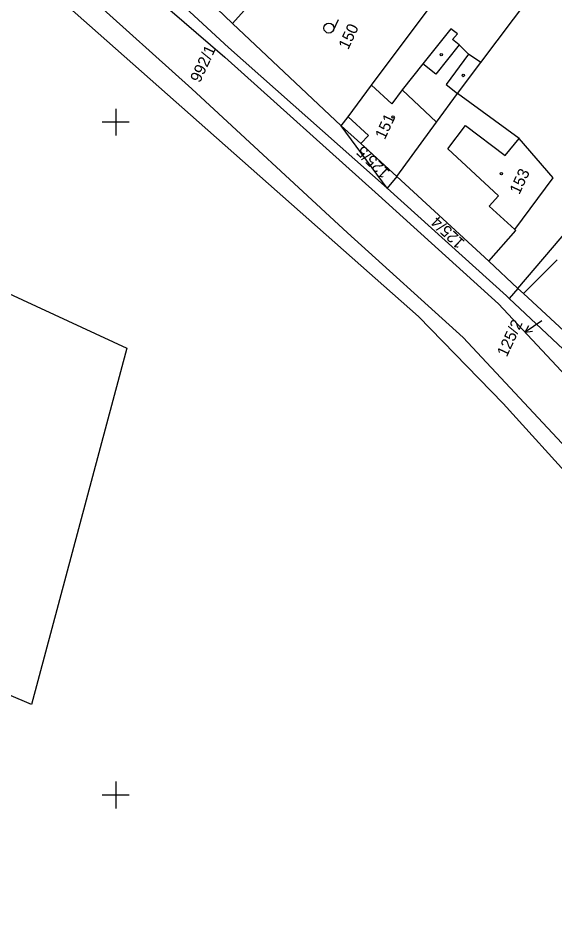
# Model space of a CAD drawing. Extents: x -755344 to -754413, y -1162670 to -1161477.
# Drawn here: x -754914.5 to -754834.8, y -1161920.2 to -1161784.6 of the extents above; entities that cross this region are included whole.
import ezdxf

# ---------------------------------------------------------------- set-up
doc = ezdxf.new("R2010")
doc.units = 0
for name, color, linetype in [('Síť', 7, 'Continuous'), ('Vrstva 55', 7, 'Continuous'), ('Vrstva 56', 7, 'Continuous'), ('Vrstva 57', 7, 'Continuous'), ('Vrstva 58', 7, 'Continuous'), ('Vrstva 59', 7, 'Continuous')]:
    doc.layers.add(name, color=color, linetype=linetype)

msp = doc.modelspace()

# ---------------------------------------------------------------- linework, layer by layer
at = {"layer": 'Síť'}
for points in [[(-754900, -1161798), (-754900, -1161800), (-754900, -1161802)], [(-754898, -1161800), (-754900, -1161800), (-754902, -1161800)], [(-754900, -1161898), (-754900, -1161900), (-754900, -1161902)], [(-754898, -1161900), (-754900, -1161900), (-754902, -1161900)]]:
    msp.add_lwpolyline(points, dxfattribs=at)
at = {"layer": 'Vrstva 55'}
for p, q in [((-754861.99, -1161794.51), (-754846.5, -1161773.77)), ((-754845.76, -1161791.14), (-754833.48, -1161774.78)), ((-754885, -1161783.11), (-754882.65, -1161785.33)), ((-754882.65, -1161785.33), (-754866.5, -1161800.56)), ((-754849.21, -1161795.73), (-754845.76, -1161791.14)), ((-754859.67, -1161809.81), (-754866.5, -1161800.56)), ((-754858.25, -1161808.07), (-754859.67, -1161809.81)), ((-754858.25, -1161808.07), (-754844.55, -1161820.66)), ((-754844.55, -1161820.66), (-754840.24, -1161824.73)), ((-754840.24, -1161824.73), (-754841.56, -1161826.18)), ((-754841.56, -1161826.18), (-754832.73, -1161834.46))]:
    msp.add_line(p, q, dxfattribs=at)
for points in [[(-754992.13, -1161692.36), (-754991.87, -1161692.75), (-754961.05, -1161719.56), (-754924.16, -1161751.14), (-754883.24, -1161788.9), (-754859.67, -1161809.81)], [(-754790.69, -1161920.17), (-754823.33, -1161865.1), (-754831.37, -1161854.01), (-754842.43, -1161841.79), (-754855.01, -1161828.87), (-754953.69, -1161741.58)], [(-754882.65, -1161785.33), (-754871.6, -1161773.02), (-754864.38, -1161779.75), (-754855.38, -1161770.09), (-754853.46, -1161767.96), (-754850.61, -1161770.4), (-754846.5, -1161773.77)], [(-754845.76, -1161791.14), (-754847.59, -1161789.9), (-754848.96, -1161788.52), (-754849.95, -1161787.73), (-754849.24, -1161786.86), (-754850.23, -1161786.13), (-754854.38, -1161791.33), (-754857.45, -1161795.19), (-754858.98, -1161797.27), (-754861.99, -1161794.51)], [(-754866.5, -1161800.56), (-754865.48, -1161799.19), (-754861.99, -1161794.51)], [(-754858.25, -1161808.07), (-754852.33, -1161799.99), (-754849.21, -1161795.73)], [(-754844.55, -1161820.66), (-754840.54, -1161816.09), (-754840.72, -1161815.93), (-754835.01, -1161808.29), (-754840.05, -1161802.42), (-754849.21, -1161795.73)], [(-754866.5, -1161800.56), (-754863.59, -1161803.15), (-754858.25, -1161808.07)], [(-754957.73, -1161806.07), (-754898.34, -1161833.59), (-754912.51, -1161886.53), (-754987.52, -1161854.57), (-755005.46, -1161846.93), (-755029.96, -1161837.42)], [(-754859.67, -1161809.81), (-754841.94, -1161825.83), (-754841.56, -1161826.18)], [(-754840.24, -1161824.73), (-754832.54, -1161815.66), (-754829.3, -1161811.83)], [(-754840.24, -1161824.73), (-754839.41, -1161825.46), (-754831.41, -1161832.91)]]:
    msp.add_lwpolyline(points, dxfattribs=at)
at = {"layer": 'Vrstva 56'}
for p, q in [((-754926.26, -1161753.63), (-754883.79, -1161790.36)), ((-754888.68, -1161795.04), (-754908.58, -1161777.13)), ((-754848.96, -1161788.52), (-754852.42, -1161792.85)), ((-754883.79, -1161790.36), (-754860.97, -1161810.87)), ((-754847.59, -1161789.9), (-754850.91, -1161794.38)), ((-754852.42, -1161792.85), (-754854.38, -1161791.33)), ((-754865.57, -1161816.45), (-754888.68, -1161795.04)), ((-754857.45, -1161795.19), (-754852.33, -1161799.99)), ((-754850.91, -1161794.38), (-754849.21, -1161795.73)), ((-754865.48, -1161799.19), (-754862.43, -1161801.96)), ((-754850.66, -1161803.98), (-754848.05, -1161800.48)), ((-754848.05, -1161800.48), (-754842.11, -1161804.93)), ((-754862.43, -1161801.96), (-754863.59, -1161803.15)), ((-754842.11, -1161804.93), (-754840.05, -1161802.42)), ((-754843.11, -1161810.92), (-754850.66, -1161803.98)), ((-754843.11, -1161827), (-754860.97, -1161810.87)), ((-754844.49, -1161812.46), (-754843.11, -1161810.92)), ((-754840.72, -1161815.93), (-754844.49, -1161812.46)), ((-754865.57, -1161816.45), (-754848.39, -1161832.02)), ((-754834.41, -1161820.45), (-754839.41, -1161825.46)), ((-754825.18, -1161846.21), (-754843.11, -1161827)), ((-754848.39, -1161832.02), (-754831.41, -1161850.21))]:
    msp.add_line(p, q, dxfattribs=at)
at = {"layer": 'Vrstva 57'}
for p, q in [((-754836.68, -1161829.53), (-754839.17, -1161831.19)), ((-754839.17, -1161831.19), (-754838.62, -1161830.22)), ((-754839.17, -1161831.19), (-754838.06, -1161831.05))]:
    msp.add_line(p, q, dxfattribs=at)
at = {"layer": 'Vrstva 58'}
msp.add_line((-754867.64, -1161786.32), (-754866.9, -1161784.74), dxfattribs=at)
msp.add_circle((-754868.32, -1161786.01), 0.75, dxfattribs=at)
at = {"layer": 'Vrstva 59'}
for centre in [(-754851.62, -1161789.96), (-754848.37, -1161793.06), (-754858.78, -1161799.22), (-754842.7, -1161807.64)]:
    msp.add_circle(centre, 0.175, dxfattribs=at)

# ---------------------------------------------------------------- texts
at = {"layer": 'Vrstva 57'}
for s, rotation, p in [('150', 65, (-754865.46, -1161789.32)), ('992/1', 65, (-754887.49, -1161794.23)), ('151', 65, (-754860.02, -1161802.69)), ('125/5', 135.6551, (-754859.15, -1161807.34)), ('153', 65, (-754840.03, -1161810.85)), ('125/4', 136.4164, (-754848.02, -1161817.76)), ('125/2', 65, (-754841.9, -1161835))]:
    msp.add_text(s, height=1.7, rotation=rotation, dxfattribs=at).set_placement(p)

doc.saveas('drawing.dxf')
